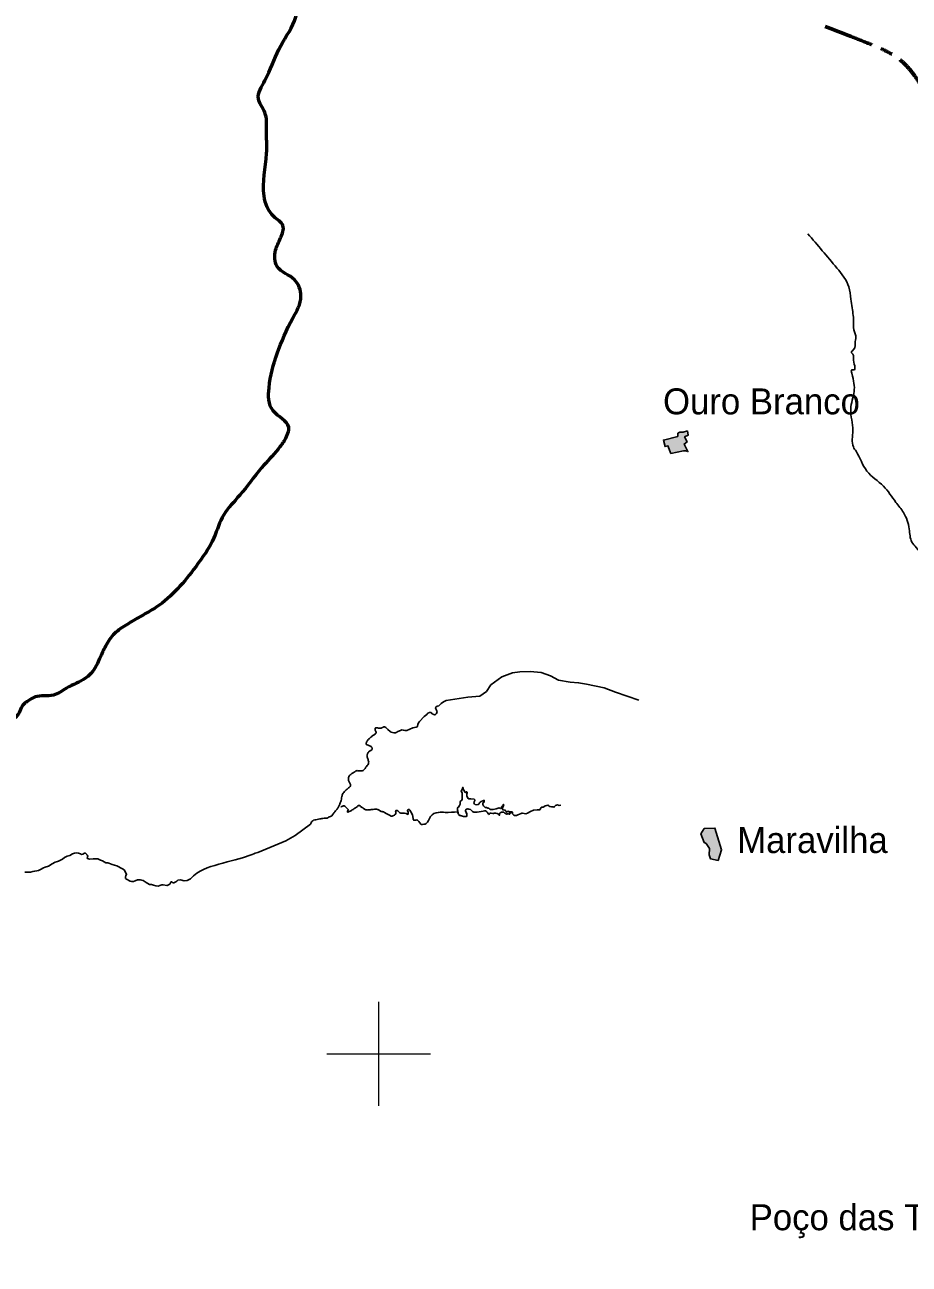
# Model space of a CAD drawing. Extents: x -1643653 to 4543381, y 1624270 to 13878484.
# Drawn here: x 668186 to 685215, y 8970948 to 8994810 of the extents above; entities that cross this region are included whole.
import ezdxf

# ---------------------------------------------------------------- set-up
doc = ezdxf.new("R2010")
doc.units = 0
doc.header["$LTSCALE"] = 160
doc.linetypes.add('LONG_DASH_SHORT_DASH', pattern=[9.9, 6, -1.2, 1.5, -1.2])
for name, color, linetype, lineweight in [('2', 7, 'Continuous', 13), ('21', 7, 'Continuous', 25), ('24', 7, 'Continuous', 25), ('60', 7, 'Continuous', 13), ('7', 7, 'LONG_DASH_SHORT_DASH', 60)]:
    doc.layers.add(name, color=color, linetype=linetype, lineweight=lineweight)
doc.layers.add('41', color=7, linetype='Continuous')

msp = doc.modelspace()

# ---------------------------------------------------------------- hatches: boundary and pattern name
at = {"layer": '21'}
for points in [[(680942.9, 8986993.5), (680862.3, 8986966.5), (680798.6, 8986964.3), (680759.6, 8986945.2), (680756.3, 8986884.4), (680481.4, 8986814.7), (680513.6, 8986689.8), (680569.2, 8986706), (680626.1, 8986558.7), (680870.3, 8986609.2), (680906.3, 8986608.9), (680953.2, 8986591.9), (680879.7, 8986736.5), (680938.2, 8986780.3), (680889.2, 8986874.9), (680956, 8986907.6)], [(681533.6, 8978720.1), (681601.7, 8978928.6), (681474.4, 8979344.4), (681268.6, 8979336), (681201.4, 8979231.2), (681264.6, 8979064.1), (681303.5, 8979046.7), (681367.3, 8978951), (681362.8, 8978827), (681387.7, 8978755.4)]]:
    msp.add_hatch(color=256, dxfattribs=at).paths.add_polyline_path(points)

# ---------------------------------------------------------------- linework, layer by layer
at = {"layer": '2'}
for p, q in [((675000, 8974000), (675000, 8976000)), ((674000, 8975000), (676000, 8975000))]:
    msp.add_line(p, q, dxfattribs=at)
at = {"layer": '21'}
for points in [[(680942.9, 8986993.5), (680862.3, 8986966.5), (680798.6, 8986964.3), (680759.6, 8986945.2), (680756.3, 8986884.4), (680481.4, 8986814.7), (680513.6, 8986689.8), (680569.2, 8986706), (680626.1, 8986558.7), (680870.3, 8986609.2), (680906.3, 8986608.9), (680953.2, 8986591.9), (680879.7, 8986736.5), (680938.2, 8986780.3), (680889.2, 8986874.9), (680956, 8986907.6)], [(681533.6, 8978720.1), (681601.7, 8978928.6), (681474.4, 8979344.4), (681268.6, 8979336), (681201.4, 8979231.2), (681264.6, 8979064.1), (681303.5, 8979046.7), (681367.3, 8978951), (681362.8, 8978827), (681387.7, 8978755.4)]]:
    msp.add_lwpolyline(points, close=True, dxfattribs=at)
at = {"layer": '24'}
msp.add_line((672671.2, 8978874.3), (672647.4, 8978867.9), dxfattribs=at)
for points in [[(680010.4, 8981805.1), (679556.9, 8981958.7), (679341.3, 8982043.7), (678998.1, 8982113.1), (678848.6, 8982142.2), (678687.8, 8982154.6), (678460.7, 8982189.8), (678306.2, 8982274.3), (678129.2, 8982336.8), (677913.1, 8982360.9), (677718.9, 8982351.5), (677574.5, 8982330.5), (677368.6, 8982254.7), (677162.1, 8982101.2), (677077.8, 8981974.5), (676949.4, 8981881.3), (676716.3, 8981866.7), (676299.8, 8981798.2), (676248, 8981776.3), (676201.9, 8981745.3), (676173.4, 8981709.8)], [(676173.4, 8981709.8), (676173, 8981709.2), (676157.8, 8981701.1), (676127.3, 8981691.6), (676101.8, 8981671.8), (676094.3, 8981657.4), (676100, 8981642), (676114.8, 8981613.2), (676125.1, 8981582.5), (676122.1, 8981566.5), (676114.4, 8981552.1), (676091.2, 8981529.2), (676075.5, 8981525.9), (676059.4, 8981529.4), (676032.2, 8981546.9), (676008.3, 8981568.8), (675992.5, 8981572.1), (675976.2, 8981569.3), (675946.6, 8981555.8), (675924.4, 8981532.2), (675899.5, 8981512.1), (675872.9, 8981493), (675787.7, 8981394.2), (675767.4, 8981368.2), (675755.3, 8981338.8), (675746.2, 8981307), (675737.7, 8981293.1), (675724.5, 8981284.2), (675659.3, 8981276.5), (675599.2, 8981251.5), (675539.1, 8981225.6), (675507.2, 8981222.6), (675475.2, 8981229.2)], [(675474, 8981229.5), (675446.5, 8981233.2), (675420.5, 8981226.1), (675370.6, 8981203.8), (675348.3, 8981188), (675322.3, 8981179), (675294.8, 8981178.1), (675267.7, 8981182.9), (675241.3, 8981190.6), (675217.6, 8981203.8), (675175.9, 8981239.8), (675137.9, 8981279), (675114.5, 8981294), (675101.3, 8981294.4), (675088.2, 8981289.5)], [(676735.1, 8979710.2), (676716.5, 8979713.3), (676699.8, 8979711.5), (676685.3, 8979701), (676673.4, 8979689.2), (676673.4, 8979670.8), (676681.3, 8979649.7), (676691.9, 8979635.3), (676697.1, 8979616.9), (676698.5, 8979598.5), (676695.8, 8979578.7), (676691.9, 8979570.9), (676670.8, 8979568.2), (676655, 8979568.2), (676631.3, 8979569.5), (676591.8, 8979578.7), (676557.6, 8979590.6), (676537.4, 8979611.3), (676526.2, 8979640.9), (676516.8, 8979711.5), (676518.1, 8979733.9), (676535.2, 8979749.7), (676548.4, 8979769.1), (676562.9, 8979792.8), (676566.8, 8979819.1), (676566.8, 8979833.5), (676568.2, 8979848), (676574.8, 8979859.8), (676593.2, 8979878.2), (676607.7, 8979899.2), (676607.7, 8979926.8), (676606.3, 8979975.5), (676605, 8980003.1), (676605, 8980020.2), (676598.4, 8980038.6), (676585.3, 8980057), (676599.8, 8980074.1), (676609, 8980103), (676616.9, 8980114.8), (676618.2, 8980128), (676626.1, 8980125.4), (676627.4, 8980108.3), (676629.1, 8980090.7), (676636.6, 8980075.4), (676656.4, 8980042.5), (676661.6, 8980030.7), (676673.5, 8980032), (676685.3, 8980039.9), (676695.9, 8980041.2), (676705.1, 8980028.1), (676697.2, 8980008.4), (676698.5, 8979987.3), (676698.5, 8979967.6), (676706.4, 8979943.9), (676716.9, 8979921.6), (676734, 8979909.8), (676749.8, 8979906.6)], [(677114.5, 8979604.9), (677115.1, 8979612.9), (677109.9, 8979626.4), (677088.3, 8979647.8), (677071.6, 8979672.7), (677058.5, 8979678.1), (677042.4, 8979678.5), (677011.8, 8979672.8), (676893.9, 8979653.4), (676833.5, 8979650.9), (676806.7, 8979663.1), (676786.2, 8979685), (676764.8, 8979705), (676734.4, 8979710.3), (676704, 8979712.9), (676679.2, 8979696.2), (676672.1, 8979684), (676673.9, 8979668.5), (676687.2, 8979642), (676697.5, 8979614.2), (676697.2, 8979584.4), (676691.5, 8979570.5), (676677.1, 8979567.8), (676646.6, 8979568.3), (676587.6, 8979579.8), (676559.2, 8979589.7), (676539.3, 8979608.2), (676527.7, 8979635), (676521.6, 8979666.9), (676517.9, 8979700.7), (676517.3, 8979732.2), (676538.4, 8979753.2), (676554.7, 8979778.5), (676566, 8979805.8), (676566.8, 8979835.9), (676569.1, 8979850.7), (676577.5, 8979863.1), (676599, 8979884.4), (676607, 8979897.2), (676609, 8979911.7), (676606.8, 8979942.2), (676605, 8980001.9), (676602.5, 8980031.5), (676585.3, 8980056.7), (676602.9, 8980080.8), (676605.9, 8980095.8), (676613.4, 8980108.1), (676616.7, 8980123.8), (676619.7, 8980128.2), (676626.8, 8980124.6), (676628.2, 8980093.8), (676656.8, 8980041), (676659.3, 8980033.3), (676664.7, 8980029.9), (676679.1, 8980035.7), (676692.6, 8980041.7), (676704.2, 8980032.5), (676701.9, 8980018), (676696.6, 8980004.1), (676698.3, 8979973.9), (676705.9, 8979945.2), (676719.6, 8979918.7), (676732.3, 8979910.4), (676746.8, 8979906.9), (676777, 8979904.4), (676836.4, 8979899), (676850.4, 8979891.1), (676851.1, 8979877.8), (676838.2, 8979849.8), (676834.1, 8979820.2), (676843.5, 8979808.4), (676856.4, 8979800.3), (676885, 8979792.4), (676915.7, 8979796.6), (676928.5, 8979805.1), (676935.4, 8979818.4), (676939.9, 8979833), (676950.8, 8979842.2), (676975.9, 8979858.9), (677004.3, 8979868.5), (677017.3, 8979875.3), (677031.4, 8979875.7), (677031.6, 8979859.5), (677027.7, 8979845.7), (677003.2, 8979827.9), (677002, 8979798), (677015.4, 8979771.4), (677036.3, 8979750.6), (677048.8, 8979742.4), (677064.8, 8979742.1), (677080.2, 8979742.2), (677089.3, 8979731.5), (677101.6, 8979725.9), (677117.8, 8979725.7), (677142.9, 8979708.9), (677155.6, 8979701.6)], [(677155.6, 8979701.6), (677170.5, 8979699.7), (677200.8, 8979701.8), (677259.5, 8979713.3), (677316.6, 8979731.3), (677344.6, 8979722.9), (677361.8, 8979724.7), (677366.5, 8979727.8), (677363.7, 8979734.2), (677362.3, 8979749.5), (677372.1, 8979760.8), (677383.9, 8979769.2), (677397.3, 8979775.5), (677399.5, 8979782.8), (677396.3, 8979789.8), (677396.1, 8979795.5), (677404.7, 8979796.3), (677412.1, 8979791.8), (677413.3, 8979785.2), (677403.4, 8979772.9), (677389.9, 8979746.9), (677386.7, 8979716.6), (677386.8, 8979701.8), (677397.3, 8979692.6), (677427.6, 8979689.4), (677443, 8979683.4), (677453.8, 8979672.6), (677454.6, 8979657.8), (677461.1, 8979653.1), (677469.3, 8979653.2), (677476.8, 8979665.5), (677489, 8979668.4), (677523.5, 8979658.6), (677553.6, 8979659.1), (677567.5, 8979655.6), (677575.8, 8979641.4), (677575.5, 8979634.3), (677568.5, 8979633), (677556.3, 8979641.9), (677526.7, 8979644.7), (677525.7, 8979637.3), (677532.1, 8979633.1), (677533.9, 8979626.8), (677527.9, 8979622.2), (677518.5, 8979611.5), (677503.8, 8979615.5), (677494.3, 8979626.8), (677486.9, 8979625.8), (677482.3, 8979619.9), (677469.5, 8979612.2), (677457.2, 8979620), (677429.7, 8979631.4), (677407.4, 8979651.1), (677377.8, 8979653.9), (677362.2, 8979653.1), (677350.3, 8979644.9), (677337.8, 8979636.6), (677328.8, 8979624.6), (677327.9, 8979593.7), (677325.9, 8979591.1), (677321.2, 8979595.4), (677308.1, 8979611.2), (677282.1, 8979626.2), (677253.3, 8979633.9), (677223.3, 8979632.2), (677209.6, 8979626.2), (677194.8, 8979625.1), (677165.1, 8979628.9), (677150.2, 8979628.9), (677136.1, 8979624), (677129.1, 8979610.6), (677115.2, 8979605.2)], [(677574.7, 8979633.6), (677579.2, 8979618), (677589.5, 8979605.1), (677602, 8979594.2), (677617.3, 8979588.8), (677650, 8979586.2), (677679.8, 8979600), (677740, 8979626.6), (677754.9, 8979633.3), (677770.9, 8979630.5), (677803, 8979623.7), (677834.8, 8979618.1), (677866.2, 8979629.4), (677923.4, 8979661), (677983.4, 8979687.5), (678048.2, 8979693.8), (678080.8, 8979695), (678098.1, 8979695.7), (678110.9, 8979703.2), (678121.9, 8979734.2), (678131.9, 8979746.2), (678148.5, 8979745), (678164.7, 8979744.1), (678179, 8979752.6), (678205.7, 8979770.8), (678236.6, 8979781.6), (678253.3, 8979785.3), (678266.6, 8979777.3), (678279, 8979766.4), (678294.1, 8979760.1), (678326.5, 8979755.5), (678358.9, 8979753.7), (678375, 8979750.2), (678382.5, 8979752.8), (678387.1, 8979759.7), (678409.9, 8979782.6), (678425.2, 8979788.5), (678441.7, 8979789.2), (678473.9, 8979781.9), (678506.3, 8979785.6)], [(675087.2, 8979659.3), (675095, 8979655.6), (675114.1, 8979645.4), (675146.7, 8979624.2), (675208.2, 8979591.3), (675240.7, 8979575.2), (675257.5, 8979573.3), (675274.6, 8979579), (675305.8, 8979595.8), (675319.4, 8979607.2), (675327.3, 8979622.7), (675327.6, 8979658.2), (675323.6, 8979674.8), (675328.6, 8979681.6), (675337.3, 8979685.4), (675354.3, 8979685.1), (675371.1, 8979678.1), (675396.3, 8979653.2), (675408.5, 8979640.4), (675424, 8979631.9), (675459.2, 8979632.5), (675494.4, 8979633.6), (675528, 8979622.3), (675560.4, 8979608.1), (675566.2, 8979614.1), (675565.7, 8979622.9), (675567.7, 8979640.6), (675564.3, 8979657.6), (675557.1, 8979673.7), (675557, 8979691.4), (675570.5, 8979702.5), (675587.8, 8979702.3), (675600.7, 8979690.3), (675618.7, 8979659.8), (675651.8, 8979597.5), (675665.5, 8979528.3), (675666.5, 8979510.4), (675673.8, 8979496.2), (675691.8, 8979495.5), (675711.8, 8979499.3), (675729.3, 8979500.5), (675745.4, 8979495.8), (675773.5, 8979473.1), (675814.3, 8979417.8), (675820.2, 8979416.2)], [(673685.8, 8979419.8), (673393.2, 8979201.1), (673214.8, 8979097.3), (672672.1, 8978875.5)], [(669373.8, 8978840), (669373.8, 8978840), (669353.6, 8978858.4), (669345.5, 8978862), (669334.7, 8978859.3), (669303.1, 8978844.9), (669277, 8978838.6), (669255.3, 8978845.8), (669219.2, 8978864.7), (669188.6, 8978866.5), (669139.9, 8978858.4), (669102, 8978849.4), (669050.6, 8978819.7), (669003.7, 8978802.6), (668952.3, 8978779.1), (668911.8, 8978746.7), (668837.1, 8978709.5), (668815.5, 8978704.1), (668767.7, 8978686.1), (668710, 8978655.5), (668639.6, 8978613.2), (668577.4, 8978592.5), (668547.7, 8978577.2), (668487.2, 8978546.6), (668447.6, 8978528.5), (668416, 8978519.5), (668377.3, 8978516.3), (668340.8, 8978510.2), (668293.7, 8978496.6), (668187.2, 8978496.2)], [(671134.5, 8978339), (671113.7, 8978325.6), (671095.8, 8978307.8), (671052.7, 8978291.4), (671034.8, 8978292.9), (671021.4, 8978300.3), (671008, 8978310.8), (670999.1, 8978304.8), (670976.7, 8978266.2), (670927.6, 8978240.9), (670918.7, 8978240.9), (670848.7, 8978251.3), (670826.4, 8978249.8), (670783.2, 8978236.4), (670752, 8978227.5), (670707.3, 8978232), (670661.2, 8978248.3), (670624, 8978255.8), (670588.4, 8978259.4), (670525.8, 8978296.6), (670464.8, 8978332.2), (670436.5, 8978339.7), (670415.7, 8978345.6), (670356.2, 8978345.6), (670310, 8978327.8), (670281.7, 8978317.4), (670243, 8978315.9), (670211.8, 8978321.8), (670146.3, 8978362), (670126.9, 8978376.8), (670125.4, 8978400.6), (670131.4, 8978430.3), (670144.8, 8978452.6), (670132.9, 8978480.9), (670097.2, 8978540.3), (670065.9, 8978562.6), (669960.2, 8978614.6), (669866.4, 8978641.4), (669806.9, 8978666.7), (669782.2, 8978675.2), (669748, 8978673.8), (669715.2, 8978693.1), (669682.5, 8978710.9), (669642.3, 8978724.3), (669591.7, 8978751), (669555.9, 8978755.5), (669505.3, 8978751), (669432.4, 8978743.6), (669393.7, 8978758.5), (669387.7, 8978773.3), (669396.7, 8978797.1), (669390.7, 8978814.9), (669381.8, 8978829.8), (669377.3, 8978834.3), (669373.8, 8978840)], [(672671.2, 8978874.3), (672647.4, 8978867.9), (672622.5, 8978859.5), (672595, 8978849.1), (672563.8, 8978837), (672527.5, 8978823.3), (672484.9, 8978808.1), (672434.6, 8978791.6), (672375.8, 8978773.9), (672309.6, 8978755.2), (672237.5, 8978735.5), (672161.1, 8978715), (672081.9, 8978693.6), (672001.4, 8978671.6), (671921.2, 8978649), (671842.8, 8978625.8), (671767.5, 8978602.1), (671695.4, 8978576.4), (671626.3, 8978547.4), (671560.2, 8978513.5), (671496.8, 8978473.3), (671436.1, 8978425.4), (671377.8, 8978368.2)], [(671377.8, 8978368.2), (671313.2, 8978332.5), (671252.5, 8978325.9), (671183, 8978348), (671134.5, 8978339)]]:
    msp.add_lwpolyline(points, dxfattribs=at)
at = {"layer": '24', "lineweight": 53}
for points in [[(673192.8, 8986819.2), (673266.9, 8987063), (672967.2, 8987378.4), (672888.4, 8987819.9), (673046.1, 8988482.3), (673345.7, 8989160.4), (673503.4, 8989586.2), (673377.3, 8989901.6), (673046.1, 8990153.9), (673014.5, 8990469.3), (673109.2, 8990705.9), (673156.5, 8990942.4), (672983, 8991115.9), (672793.8, 8991510.2), (672841.1, 8992330.2), (672841.1, 8992787.6), (672809.5, 8993118.7), (672683.4, 8993386.8), (672809.5, 8993733.8), (673077.6, 8994335.6), (673377.3, 8994887.9), (673519.2, 8995534.8), (673535, 8995976.6), (673487.7, 8996159.6), (673676.9, 8996349), (674008.1, 8996727.7), (674355, 8997327.2), (674512.7, 8997705.9), (674843.9, 8997895.2), (675080.4, 8998053), (675033.1, 8998242.4), (675144.3, 8998385.5)], [(673192.8, 8986819.2), (673063.2, 8986639.7), (672744, 8986280.6), (672325.1, 8985752), (672015.9, 8985373), (671826.4, 8984934.1), (671477.3, 8984375.6), (670717.7, 8983597.6), (670425.1, 8983424.8), (670155.8, 8983265.2), (669913.1, 8983089), (669740.3, 8982846.3), (669627.2, 8982610.2), (669494.2, 8982364.2), (669361.2, 8982234.6), (668988.9, 8982038.4), (668736.2, 8981905.4), (668383.8, 8981868.8), (668230.9, 8981779.1)], [(668235.4, 8981781.7), (668180.4, 8981742.1), (668134.2, 8981686.6), (668075.1, 8981562.7), (668027, 8981492.5), (667967.9, 8981461), (667921.7, 8981488.8), (667871.8, 8981544.2), (667781.2, 8981597.9), (667585.3, 8981649.6), (667500.3, 8981618.2), (667420.8, 8981547.9), (667309.9, 8981425.9), (667293.3, 8981368.6), (667232.3, 8981272.4), (667158.4, 8981204), (667071.5, 8981167), (666929.2, 8981074.6), (666877.5, 8980963.6), (666866.4, 8980874.9)]]:
    msp.add_spline(points, degree=3, dxfattribs=at)
at = {"layer": '24'}
for points in [[(687252.8, 8980199.7), (687166.4, 8980215.3), (687101.2, 8980261.9), (687040.7, 8980308.5), (686970.8, 8980317.8), (686901, 8980317.8), (686742.7, 8980252.6), (686575, 8980285.2), (686332.9, 8980415.6), (686239.8, 8980462.2), (686267.7, 8980560.1), (686249.1, 8980648.6), (686319, 8980867.6), (686603, 8981398.7), (686663.5, 8981524.5), (686724, 8981794.7), (686910.3, 8982102.2), (686952.2, 8982386.4), (686942.9, 8982470.3), (686854.4, 8982554.2), (686873, 8982684.6), (686868.4, 8982926.9), (686789.2, 8983094.6), (686770.6, 8983220.4), (686770.6, 8983276.3), (686649.6, 8983392.8), (686528.5, 8983527.9), (686481.9, 8983644.4), (686337.6, 8983709.6), (686104.8, 8983905.3), (686007, 8984026.5), (685834.7, 8984133.6), (685350.5, 8984748.6), (685266.7, 8984851.1), (685215.5, 8985102.7), (685103.7, 8985419.5), (684959.4, 8985615.2), (684717.3, 8985927.4), (684400.6, 8986216.2), (684191.1, 8986598.3), (684139.9, 8986682.2), (684130.6, 8986994.3), (684088.7, 8987409), (684153.8, 8987749.1), (684107.3, 8988103.2), (684107.3, 8988163.8), (684139.9, 8988163.8), (684139.9, 8988382.8), (684144.5, 8988434), (684116.6, 8988480.6), (684102.6, 8988494.6), (684144.5, 8988555.1), (684177.1, 8988713.5), (684186.5, 8988820.7), (684158.5, 8988895.2), (684144.5, 8989067.6), (684116.6, 8989361.2), (684093.3, 8989528.9), (684051.4, 8989761.8), (683823.3, 8990125.3), (683259.9, 8990786.8)], [(673192.8, 8986819.2), (673063.2, 8986639.7), (672744, 8986280.6), (672325.1, 8985752), (672015.9, 8985373), (671826.4, 8984934.1), (671477.3, 8984375.6), (670717.7, 8983597.6), (670425.1, 8983424.8), (670155.8, 8983265.2), (669913.1, 8983089), (669740.3, 8982846.3), (669627.2, 8982610.2), (669494.2, 8982364.2), (669361.2, 8982234.6), (668988.9, 8982038.4), (668736.2, 8981905.4), (668383.8, 8981868.8), (668230.9, 8981779.1)], [(668235.4, 8981781.7), (668180.4, 8981742.1), (668134.2, 8981686.6), (668075.1, 8981562.7), (668027, 8981492.5), (667967.9, 8981461), (667921.7, 8981488.8), (667871.8, 8981544.2), (667781.2, 8981597.9), (667585.3, 8981649.6), (667500.3, 8981618.2), (667420.8, 8981547.9), (667309.9, 8981425.9), (667293.3, 8981368.6), (667232.3, 8981272.4), (667158.4, 8981204), (667071.5, 8981167), (666929.2, 8981074.6), (666877.5, 8980963.6), (666866.4, 8980874.9)], [(675820.2, 8979416.2), (675913.3, 8979430.9), (675996.6, 8979568.1), (676148.5, 8979646.5), (676280.7, 8979646.5), (676520.8, 8979656.2)]]:
    msp.add_spline(points, degree=3, dxfattribs=at)
for points in [[(675088.2, 8981289.5), (675084.6, 8981286.1), (675073.1, 8981281), (675059.7, 8981272.7), (675039.9, 8981265.7), (675019.6, 8981265.6), (674995.4, 8981268.7), (674982, 8981273.1), (674960.3, 8981278.1), (674940.6, 8981276.2), (674934.2, 8981266.7), (674930.4, 8981246.4), (674930.3, 8981233.3), (674939.2, 8981216.9), (674950, 8981194.1), (674950, 8981172.6), (674932.2, 8981151.7), (674910.5, 8981138.4), (674888.2, 8981126.9), (674870.8, 8981114.5), (674849.1, 8981094.2), (674823.7, 8981070.8), (674802, 8981051.2), (674784.8, 8981030.3), (674766.2, 8981002.1), (674758, 8980979.3), (674754.2, 8980961.6), (674762.4, 8980950.3), (674795.5, 8980943.4), (674824.7, 8980928.9), (674855.4, 8980911.6), (674866.2, 8980896.4), (674876.3, 8980876.2), (674874.2, 8980857.5), (674852.5, 8980838.7), (674834.8, 8980830.4), (674816.2, 8980826.5), (674798.8, 8980797.3), (674785.8, 8980771.4), (674778.7, 8980757.7), (674774.3, 8980746.3), (674774.3, 8980730.6), (674779.7, 8980710.9), (674789.6, 8980677.2), (674799.5, 8980647.8), (674809.4, 8980612.7), (674805.2, 8980583.2), (674774.2, 8980544.7), (674750.3, 8980520.8), (674739, 8980494.1), (674719.4, 8980460.5), (674681.4, 8980447.8), (674633.7, 8980443.5), (674600.1, 8980450.4), (674572.5, 8980450.3), (674553, 8980439), (674525.2, 8980417.8), (674494.6, 8980402.3), (674473.2, 8980385.5), (674449, 8980368.7), (674429.1, 8980349.2), (674417.7, 8980318.3), (674418.2, 8980300.5), (674418.2, 8980271.1), (674421.1, 8980248.6), (674435.4, 8980221.9), (674452.6, 8980193.8), (674461.2, 8980171.3), (674452.6, 8980146.1), (674437, 8980126.5), (674405.6, 8980106.4), (674374.2, 8980081.3), (674342.8, 8980050.5), (674311.5, 8980012.7), (674298.6, 8979983.2), (674290.1, 8979952.4), (674283, 8979903.3), (674270.2, 8979852.8), (674250.5, 8979810.5), (674243.8, 8979793.3), (674225.4, 8979755.1)], [(674225.4, 8979755.1), (674222.2, 8979749.1), (674211.1, 8979728.9), (674193.8, 8979701.7), (674168, 8979673.7), (674143.7, 8979647.1), (674129.5, 8979619.1), (674096.6, 8979574.2), (674050.8, 8979561.7), (674019.3, 8979542.1), (673990.7, 8979533.8), (673947.8, 8979533.8), (673904.9, 8979528.3), (673866.3, 8979522.8), (673814.8, 8979508.9), (673766.2, 8979501.9), (673727.5, 8979486.2), (673707.4, 8979468.8), (673695.9, 8979444.3), (673685.8, 8979419.8)], [(674269.9, 8979755.2), (674271, 8979755.6), (674281, 8979758.8), (674301.5, 8979764.1), (674322.1, 8979771.7), (674348.5, 8979771.6), (674363.3, 8979753.9), (674372.3, 8979741.2), (674378.3, 8979735)], [(674378.3, 8979735), (674384.3, 8979728.8), (674399.4, 8979716.5), (674413.6, 8979702), (674406.5, 8979679.2), (674395.3, 8979662.6), (674398.5, 8979650.6), (674415.9, 8979653.8), (674449.4, 8979671.4), (674501.4, 8979697.8), (674579.8, 8979752.3), (674601.8, 8979771.3), (674617.6, 8979782), (674634.1, 8979778.8), (674651.9, 8979763), (674669.8, 8979744), (674693.9, 8979732.5), (674719.3, 8979715.9), (674739.1, 8979699.9), (674757.5, 8979693.5), (674779.1, 8979691.4), (674805.7, 8979694.5), (674831.1, 8979699.4), (674872.3, 8979701.7), (674917.4, 8979707.8), (674962.5, 8979706.9), (674989.8, 8979703.6), (675008.2, 8979692.1), (675027.3, 8979672.9), (675045.8, 8979662.6), (675065.5, 8979660.6), (675080.1, 8979660.5), (675087.2, 8979659.3)]]:
    msp.add_open_spline(points, degree=3, dxfattribs=at)
at = {"layer": '60', "lineweight": 25}
msp.add_spline([(814781, 9009175.5), (814787.2, 9009173.4), (814796.9, 9009173.4), (814799.4, 9009172.4), (814805.1, 9009174.5), (814805.6, 9009176.5), (814811.7, 9009179.5), (814811.7, 9009179.5), (814801.5, 9009181), (814790.7, 9009181.5), (814784.1, 9009183.1), (814777.4, 9009185.1), (814778.4, 9009175.5)], degree=3, dxfattribs=at)
at = {"layer": '7'}
msp.add_spline([(683598.6, 8994777.1), (684397.7, 8994464.4), (685057.9, 8994117), (685335.8, 8993804.3), (685509.6, 8993491.6), (685648.5, 8993005.2), (685787.5, 8992692.5), (686065.5, 8992275.5), (686343.4, 8991858.6), (686725.6, 8991615.4), (687073, 8991302.7), (687420.5, 8990920.5), (687906.9, 8989912.9), (688323.8, 8989079.1), (688636.5, 8988384.2), (688984, 8987863), (689435.6, 8987654.6), (689817.8, 8987515.6), (690269.5, 8987168.1), (690582.2, 8986959.7), (690825.4, 8986994.4), (691033.9, 8986716.5), (691311.8, 8986369), (691902.5, 8985500.4), (692354.1, 8985153), (692666.8, 8984701.3), (692875.3, 8984214.9), (693158.7, 8983934.4), (693502.3, 8983815), (693545.2, 8983676.6), (693602.5, 8983504.7), (693621.6, 8983017.8), (693570.2, 8982929.4), (693397.3, 8982487.9), (693500.7, 8982373.5), (693769.5, 8982043.9), (693907.8, 8981934.1), (694056.6, 8981574.3), (694126.1, 8980775.2), (694195.6, 8980288.8), (694332.5, 8979985.6), (694542.5, 8979770.8), (694432.7, 8979351), (694365.9, 8979193.5), (694122.6, 8978945.4), (693898.3, 8978539.8), (694012.8, 8978253.5), (694475.7, 8978549.3), (695243.9, 8979169.6), (695396.6, 8979322.3), (696002.5, 8979718.4), (696732.6, 8980376.8), (697123.8, 8980615.4), (697739.5, 8980636.2), (698156.4, 8980636.2)], degree=3, dxfattribs=at)

# ---------------------------------------------------------------- texts
at = {"layer": '41'}
for s, p in [('Ouro Branco', (680474.5, 8987309.9)), ('Maravilha', (681902.6, 8978864.1)), ('Poço das Trincheiras', (682142.8, 8971602.3))]:
    msp.add_text(s, height=500, dxfattribs=at).set_placement(p)

doc.saveas('drawing.dxf')
